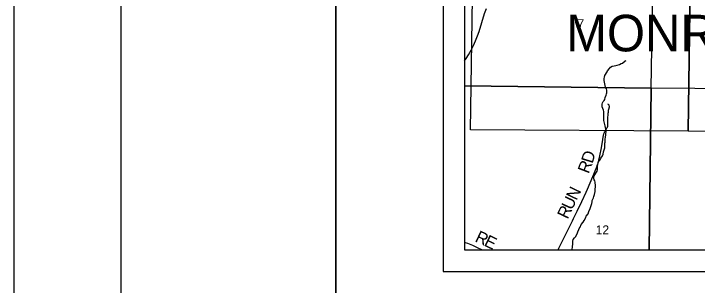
# Model space of a CAD drawing. Extents: x -19.9 to 41.9, y 0 to 32.3.
# Drawn here: x 0 to 3.184, y 13.935 to 15.201 of the extents above; entities that cross this region are included whole.
import ezdxf

# ---------------------------------------------------------------- set-up
doc = ezdxf.new("R2010")
doc.units = 0
for name, color, linetype in [('GM_X_Corporation', 7, 'Continuous'), ('GM_X_County_Road', 7, 'Continuous'), ('GM_X_County_Road_Text', 7, 'Continuous'), ('GM_X_Minor_River', 7, 'Continuous'), ('GM_X_Rail_Line', 7, 'Continuous'), ('GM_X_Section', 7, 'Continuous'), ('GM_X_Section_Text', 7, 'Continuous'), ('GM_X_Township_Road', 7, 'Continuous'), ('GM_X_Township_Road_Text', 7, 'Continuous'), ('GM_X_Township_Text', 7, 'Continuous'), ('SH_Border', 7, 'Continuous'), ('SH_Cut_Line', 7, 'Continuous'), ('SH_Data', 7, 'Continuous')]:
    doc.layers.add(name, color=color, linetype=linetype)

msp = doc.modelspace()

# ---------------------------------------------------------------- linework, layer by layer
at = {"layer": 'GM_X_Corporation'}
for points in [[(2.1, 17.918), (2.1, 14.1), (8.9, 14.1), (8.9, 17.8974), (7.9072, 17.9171), (7.5529, 17.9242), (7.3858, 17.9277), (6.9468, 17.937), (6.7, 17.9422), (6.3069, 17.9505), (6.2497, 17.9517), (6.2397, 17.9517), (5.9048, 17.9534), (5.761, 17.9543), (5.4954, 17.9559), (5.0257, 17.9637), (5.0192, 17.8403), (4.9169, 17.8392), (4.2613, 17.8672), (3.984, 17.879), (3.7505, 17.884), (2.973, 17.9007), (2.4715, 17.9106)], [(2.1, 15.8858), (2.1, 14.8643), (2.9693, 14.8541), (2.9854, 15.8784)], [(2.9854, 15.8784), (3.9969, 15.8607), (3.9837, 14.8466), (2.9693, 14.8541)], [(2.1, 14.8643), (2.1, 14.1), (2.9597, 14.1), (2.9693, 14.8541)], [(2.9597, 14.1), (3.9655, 14.1), (3.9837, 14.8466), (2.9693, 14.8541)]]:
    msp.add_lwpolyline(points, close=True, dxfattribs=at)
msp.add_lwpolyline([(2.1, 17.918), (2.1, 14.1), (7.8246, 14.1), (7.8518, 15.3043), (7.854, 15.4058), (7.8702, 16.1679), (7.8776, 16.5173), (7.9012, 17.4524), (7.9072, 17.9171)], dxfattribs=at)
at = {"layer": 'GM_X_County_Road'}
msp.add_lwpolyline([(2.1806, 14.1), (2.1606, 14.1097), (2.1541, 14.1129), (2.1473, 14.1161), (2.1386, 14.1203), (2.1303, 14.1239), (2.1234, 14.1267), (2.1158, 14.1297), (2.105, 14.1336), (2.1, 14.1354)], dxfattribs=at)
at = {"layer": 'GM_X_Minor_River'}
for points in [[(2.7026, 14.3493), (2.7047, 14.3592), (2.7076, 14.3726), (2.7086, 14.3783), (2.7089, 14.3848), (2.7096, 14.3928), (2.7094, 14.4038), (2.7089, 14.4107), (2.7081, 14.4164), (2.7061, 14.4221), (2.7041, 14.427), (2.7018, 14.4346), (2.7024, 14.4422), (2.712, 14.4587), (2.7172, 14.4679), (2.7186, 14.4748), (2.7192, 14.4824), (2.7195, 14.49), (2.7205, 14.4965), (2.7227, 14.5072), (2.7275, 14.5149), (2.7308, 14.5203), (2.7352, 14.5272), (2.743, 14.538), (2.7448, 14.546), (2.7473, 14.5571), (2.748, 14.5628), (2.7527, 14.5758), (2.7526, 14.5807), (2.7536, 14.5914), (2.7539, 14.5975), (2.7542, 14.6028), (2.7545, 14.6093), (2.7555, 14.6158), (2.7569, 14.6265), (2.7575, 14.6364), (2.7585, 14.6436), (2.7588, 14.6497), (2.7586, 14.6619), (2.757, 14.6706), (2.7546, 14.6786), (2.7514, 14.6915), (2.7486, 14.7028), (2.7481, 14.7085), (2.7488, 14.7146), (2.749, 14.7253), (2.7489, 14.7337), (2.7487, 14.7447), (2.7467, 14.7512), (2.7436, 14.7595), (2.7412, 14.7678), (2.7403, 14.7796), (2.7417, 14.7865), (2.7454, 14.7922), (2.7506, 14.7965), (2.7528, 14.8019), (2.7553, 14.8107), (2.7589, 14.8218), (2.7615, 14.8275), (2.7629, 14.8329), (2.7629, 14.8393), (2.762, 14.8454), (2.7604, 14.8511), (2.7569, 14.8586), (2.7553, 14.8662), (2.7525, 14.8738), (2.75, 14.8897), (2.7495, 14.8996), (2.7509, 14.9057), (2.7534, 14.913), (2.7642, 14.9303), (2.7656, 14.9353), (2.7742, 14.9461), (2.779, 14.9519), (2.788, 14.9573), (2.7971, 14.959), (2.805, 14.9602), (2.8103, 14.9615), (2.8212, 14.9651), (2.8287, 14.9686), (2.8355, 14.9714), (2.8479, 14.9818), (2.8528, 14.9827)], [(2.5999, 14.1), (2.6006, 14.1022), (2.6023, 14.1144), (2.604, 14.1289), (2.6035, 14.135), (2.6042, 14.1415), (2.6064, 14.1484), (2.6112, 14.1572), (2.616, 14.1619), (2.6241, 14.1757), (2.6274, 14.1837), (2.6314, 14.1956), (2.6344, 14.2006), (2.6377, 14.206), (2.6428, 14.2194), (2.6525, 14.2298), (2.6569, 14.2371), (2.6647, 14.2513), (2.6661, 14.2582), (2.6762, 14.269), (2.6794, 14.2789), (2.6853, 14.2935), (2.6885, 14.303), (2.6911, 14.3111), (2.6933, 14.3168), (2.6939, 14.3248), (2.6946, 14.3305), (2.6997, 14.3436), (2.7026, 14.3493)]]:
    msp.add_lwpolyline(points, dxfattribs=at)
at = {"layer": 'GM_X_Rail_Line'}
msp.add_lwpolyline([(2.1, 14.9817), (2.107, 14.9921), (2.1177, 15.009), (2.1306, 15.0315), (2.141, 15.0526), (2.1513, 15.0751), (2.1609, 15.0988), (2.1673, 15.1184), (2.1805, 15.1601), (2.1933, 15.2014), (2.2021, 15.2252)], dxfattribs=at)
at = {"layer": 'GM_X_Section'}
for points in [[(2.1434, 15.6849), (3.155, 15.6672), (3.1417, 14.6532), (2.1273, 14.6606)], [(3.155, 15.6672), (4.1589, 15.6469), (4.1452, 14.714), (4.1443, 14.6461), (3.1417, 14.6532)]]:
    msp.add_lwpolyline(points, close=True, dxfattribs=at)
at = {"layer": 'GM_X_Township_Road'}
msp.add_lwpolyline([(2.5355, 14.1), (2.5393, 14.1077), (2.5714, 14.1738), (2.6019, 14.2363), (2.6068, 14.2459), (2.6246, 14.2811), (2.6313, 14.2948), (2.6392, 14.3114), (2.6459, 14.3255), (2.6664, 14.3699), (2.6724, 14.3834), (2.6852, 14.4131), (2.6973, 14.4417), (2.7052, 14.4611), (2.7154, 14.4869), (2.7198, 14.4985), (2.7221, 14.505), (2.7236, 14.5102), (2.726, 14.5194), (2.7288, 14.5312), (2.7335, 14.5537), (2.7348, 14.5604), (2.7361, 14.5682), (2.7431, 14.6126), (2.7438, 14.6164), (2.7473, 14.6334), (2.7491, 14.6416), (2.7499, 14.6443), (2.7509, 14.6473), (2.7521, 14.6501), (2.7527, 14.6513), (2.7643, 14.6714), (2.765, 14.6728), (2.7666, 14.6767), (2.7671, 14.6785), (2.7673, 14.6803), (2.7676, 14.6862), (2.7678, 14.6987), (2.7679, 14.7205), (2.7682, 14.7265), (2.769, 14.7375), (2.7696, 14.7427), (2.771, 14.7517), (2.772, 14.7565), (2.7742, 14.7667), (2.7744, 14.7685), (2.7741, 14.772), (2.7736, 14.7736), (2.7726, 14.7753), (2.7714, 14.7769), (2.7698, 14.7786), (2.7677, 14.7801)], dxfattribs=at)
at = {"layer": 'SH_Border'}
for points in [[(0.5, 21.5), (1.5, 21.5), (1.5, 0.5), (0.5, 0.5)], [(1.5, 21.5), (33.5, 21.5), (33.5, 0.5), (1.5, 0.5)]]:
    msp.add_lwpolyline(points, close=True, dxfattribs=at)
at = {"layer": 'SH_Cut_Line'}
msp.add_lwpolyline([(0, 0), (34, 0), (34, 22), (0, 22)], close=True, dxfattribs=at)
at = {"layer": 'SH_Data'}
for p, q in [((2, 21), (2, 14)), ((2.1, 20.9), (2.1, 14.1)), ((2.1, 14.1), (8.9, 14.1)), ((2.1, 14.1), (2.1, 14.1)), ((2, 14), (9, 14))]:
    msp.add_line(p, q, dxfattribs=at)

# ---------------------------------------------------------------- texts
at = {"layer": 'GM_X_County_Road_Text'}
for s, rotation, p in [('R', 334.9266, (2.1448, 14.1412)), ('E', 334.3559, (2.1869, 14.1215))]:
    msp.add_text(s, height=0.0568, rotation=rotation, dxfattribs=at).set_placement(p)
at = {"layer": 'GM_X_Section_Text'}
for s, height, p in [('7', 0.0419, (2.6258, 15.1338)), ('12', 0.04186, (2.7108, 14.1728))]:
    msp.add_text(s, height=height, rotation=0, dxfattribs=at).set_placement(p)
at = {"layer": 'GM_X_Township_Road_Text'}
for s, rotation, p in [('D', 73.0228, (2.6958, 14.5001)), ('R', 68.8871, (2.6776, 14.4524)), ('N', 64.3734, (2.6214, 14.3276)), ('U', 64.5363, (2.5999, 14.2825)), ('R', 64.5382, (2.5798, 14.2404))]:
    msp.add_text(s, height=0.0568, rotation=rotation, dxfattribs=at).set_placement(p)
at = {"layer": 'GM_X_Township_Text'}
msp.add_text('MONROE', height=0.17045, rotation=0, dxfattribs=at).set_placement((2.5732, 15.0257))

doc.saveas('drawing.dxf')
